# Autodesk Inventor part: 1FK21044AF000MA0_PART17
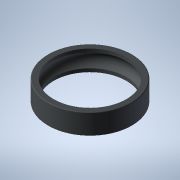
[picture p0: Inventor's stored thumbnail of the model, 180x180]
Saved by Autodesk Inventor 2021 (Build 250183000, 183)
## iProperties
Created: 2025-04
Part Number: 1FK21044AF000MA0_PART17
Material: Generic
Catalog Web Link: www.3dfindit.com
Description: -Servo synchronous motor
Document SubType Name: Modeling
Designer: psAdmin
Mass: 1.64389 g
Surface Area: 26.4305 cm^2
Volume: 1.64389 cm^3
Density: 1 g/cm^3
Appearance: PSOLRGB-212-217-219
Category: PARTsolutions
Title: 1FK21044AF000MA0_PART17
Author: Cadenas PARTsolutions
Comments: Servo synchronous motor
Sending System: PARTsolutions
Preprocessor: ST-DEVELOPER v19.3
PSOL_IDENT_0: {$CADENAS_DATA/23d-libs/siemens_ag/_cat_/39/c4/1fk21044af000ma0.prj},216 {VTYP=3D},{NB=1FK21044AF000
PSOL_IDENT_1: MA0_PART17},{LINA=1FK21044AF000MA0_PART17},{NN=1FK21044AF000MA0_PART17},{NOPRJ=TRUE},{DATE=19.08.202
PSOL_IDENT_2: 5 14:00:33},{GEOMDATE=30.07.2025 02:02:22},{VERSION=},{LINEID=10},{WBVAR=},{WBNUMERIC=}  {NB=1FK2104
PSOL_IDENT_3: 4AF000MA0_PART17},{LINA=1FK21044AF000MA0_PART17},{KT=DUMMY},{PREVIEW=../../../_pool_/cb/72/p_d211_xx
PSOL_IDENT_4: _00434j.png},{DESCSHORT=SIMOTICS S-1FK2 HD, SINAMICS S210 3AC 400V-480V, 1.27 Nm, 3000 rpm},{DESCLON
PSOL_IDENT_5: G=SIMOTICS S-1FK2 HD servo motor M0=1.27 Nm; PN = 0.4 kW at nN=3000 rpm (380-480 V); PN = 0.2 kW at
PSOL_IDENT_6: nN=1500 rpm (200-240 V); degree of protection IP64; cylindrical shaft D19x40mm; absolute encoder 22-
PSOL_IDENT_7: bit + 12-bit multiturn (encoder AM22DQC); with OCC interface; plug size M17, rotatable; SIMOTICS S-1
PSOL_IDENT_8: FK2 servomotorfor a wide range of uses in industrial environments. SIMOTICS S‑1FK2 servomotors are c
PSOL_IDENT_9: ompact synchronous motors with a high dynamic performance that set themselves apart as a result of t
PSOL_IDENT_10: heir high power density, degree of protection and overload capability. The motors are available in t
PSOL_IDENT_11: wo variants: as High Dynamic variant (highest dynamic performance as a result of the low intrinsic m
PSOL_IDENT_12: oment of inertia for applications demanding a high dynamic performance with low moved masses) - and
PSOL_IDENT_13: as Compact variant (precise and stable closed-loop control for medium up to large moved masses as a
PSOL_IDENT_14: result of a medium intrinsic moment of inertia). SIMOTICSS‑1FK2 servomotors fully exploit their stre
PSOL_IDENT_15: ngths in a system with the SINAMICSS210 frequency converter and simple connection using the one cabl
PSOL_IDENT_16: e connection (OCC). Advantages include the short control and positioning times, fast and precise cor
PSOL_IDENT_17: rection of disturbing quantities as well as stable control with a high dynamic performance. The serv
PSOL_IDENT_18: o motors can be configured to address a wide range of requirements. For example with and without hol
PSOL_IDENT_19: ding brake, IP64 or IP65 degree of protection, singleturn or multiturn absolute encoders - to name j
PSOL_IDENT_20: ust a few. Further, the servomotors are available in different shaft heights extending from 20 to 10
PSOL_IDENT_21: 0. A shaft sealing ring is available to achieve an IP65 degree of protection and for subsequent moun
PSOL_IDENT_22: ting at the motor or as spare part. SIMOTICS - the optimum motor for each and every motion control a
PSOL_IDENT_23: pplication.},{INTNO=804766906428},{SUPPLIERALTNO=1FK2104-4AF00-0MA0},{MANUID=1FK21044AF000MA0},{MANU
PSOL_IDENT_24: NAME=Siemens},{MANUTYPEDESC=Synchronous motor 1FK2-HD 1.27 NM},{AAU732=SIMOTICS},{AAO057=S-1FK2},{AA
PSOL_IDENT_25: U734=SIMOTICS S-1FK2 HD servo motor M0=1.27 Nm; PN = 0.4 kW at nN=3000 rpm (380-480 V); PN = 0.2 kW
PSOL_IDENT_26: at nN=1500 rpm (200-240 V); degree of protection IP64; cylindrical shaft D19x40mm; absolute encoder
PSOL_IDENT_27: 22-bit + 12-bit multiturn (encoder AM22DQC); with OCC interface; plug size M17, rotatable;},{AAW338=
PSOL_IDENT_28: Synchronous motor 1FK2-HD 1.27 NM},{AAO742=SIMOTICS},{AAO663=4042948693322},{NOCUPEROU=1},{PRICEQUAN
PSOL_IDENT_29: TITY=1},{QUANTITYMIN=1},{QUANTITYINT=1},{CTN=85015100},{COO=DE},{AAO676=1FK2104-4AF00-0MA0},{AAO677=
PSOL_IDENT_30: Siemens AG},{ORDERUNIT=C62},{CONTENTUNIT=C62}
NB: 1FK21044AF000MA0_PART17
NT: Servo synchronous motor
NBSYN: $MANUID._PART17
LINA: 1FK21044AF000MA0_PART17
CATALOG: SIEMENS
PREVIEW: ../../../_pool_/cb/72/p_d211_xx_00434j.png
DESCSHORT: SIMOTICS S-1FK2 HD, SINAMICS S210 3AC 400V-480V, 1.27 Nm, 3000 rpm
DESCLONG: SIMOTICS S-1FK2 HD servo motor M0=1.27 Nm; PN = 0.4 kW at nN=3000 rpm (380-480 V); PN = 0.2 kW at nN=1500 rpm (200-240 V); degree of protection IP64; cylindrica
INTNO: 804766906428
SUPPLIERALTNO: 1FK2104-4AF00-0MA0
MANUID: 1FK21044AF000MA0
MANUNAME: Siemens
MANUTYPEDESC: Synchronous motor 1FK2-HD 1.27 NM
AAU732: SIMOTICS
AAO057: S-1FK2
AAU734: SIMOTICS S-1FK2 HD servo motor M0=1.27 Nm; PN = 0.4 kW at nN=3000 rpm (380-480 V); PN = 0.2 kW at nN=1500 rpm (200-240 V); degree of protection IP64; cylindrica
AAW338: Synchronous motor 1FK2-HD 1.27 NM
AAO742: SIMOTICS
AAO663: 4042948693322.0
NOCUPEROU: 1
PRICEQUANTITY: 1
QUANTITYMIN: 1
QUANTITYINT: 1
CTN: 85015100
COO: DE
ARTICLENO: 1FK21044AF000MA0_PART17
BOMINFO: 1FK21044AF000MA0_PART17
CREATOR: CADENAS GmbH
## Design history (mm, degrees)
feature "2025_04_17_15_01_28_0038"
body "Solid1"
